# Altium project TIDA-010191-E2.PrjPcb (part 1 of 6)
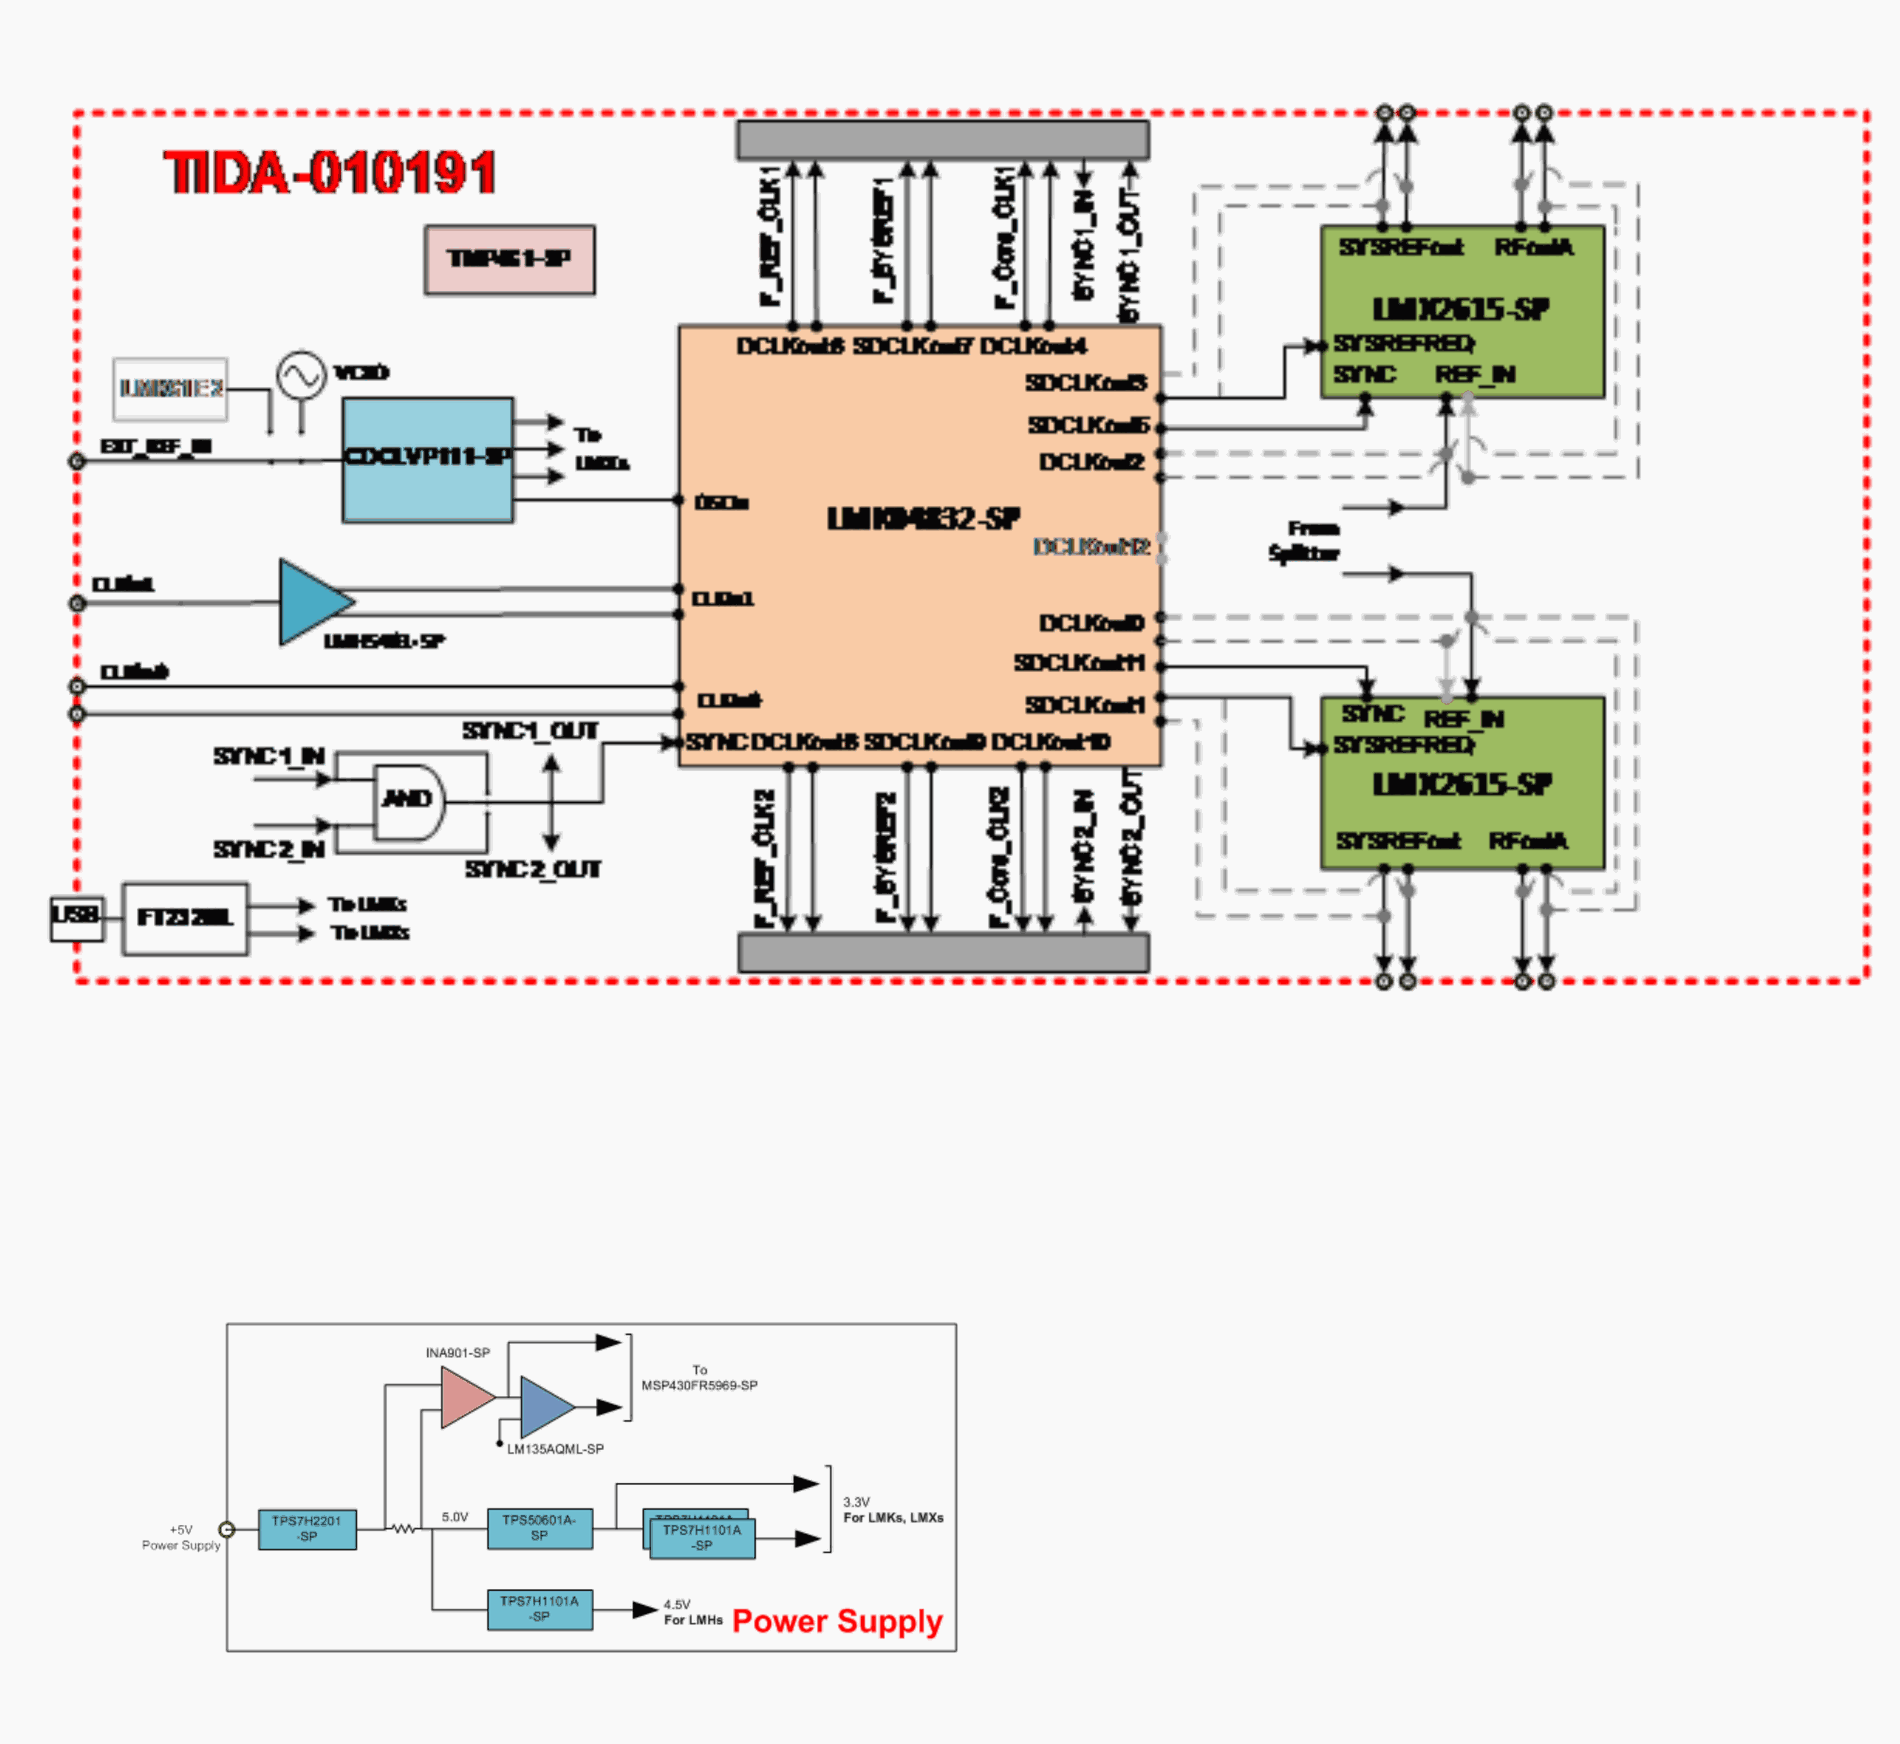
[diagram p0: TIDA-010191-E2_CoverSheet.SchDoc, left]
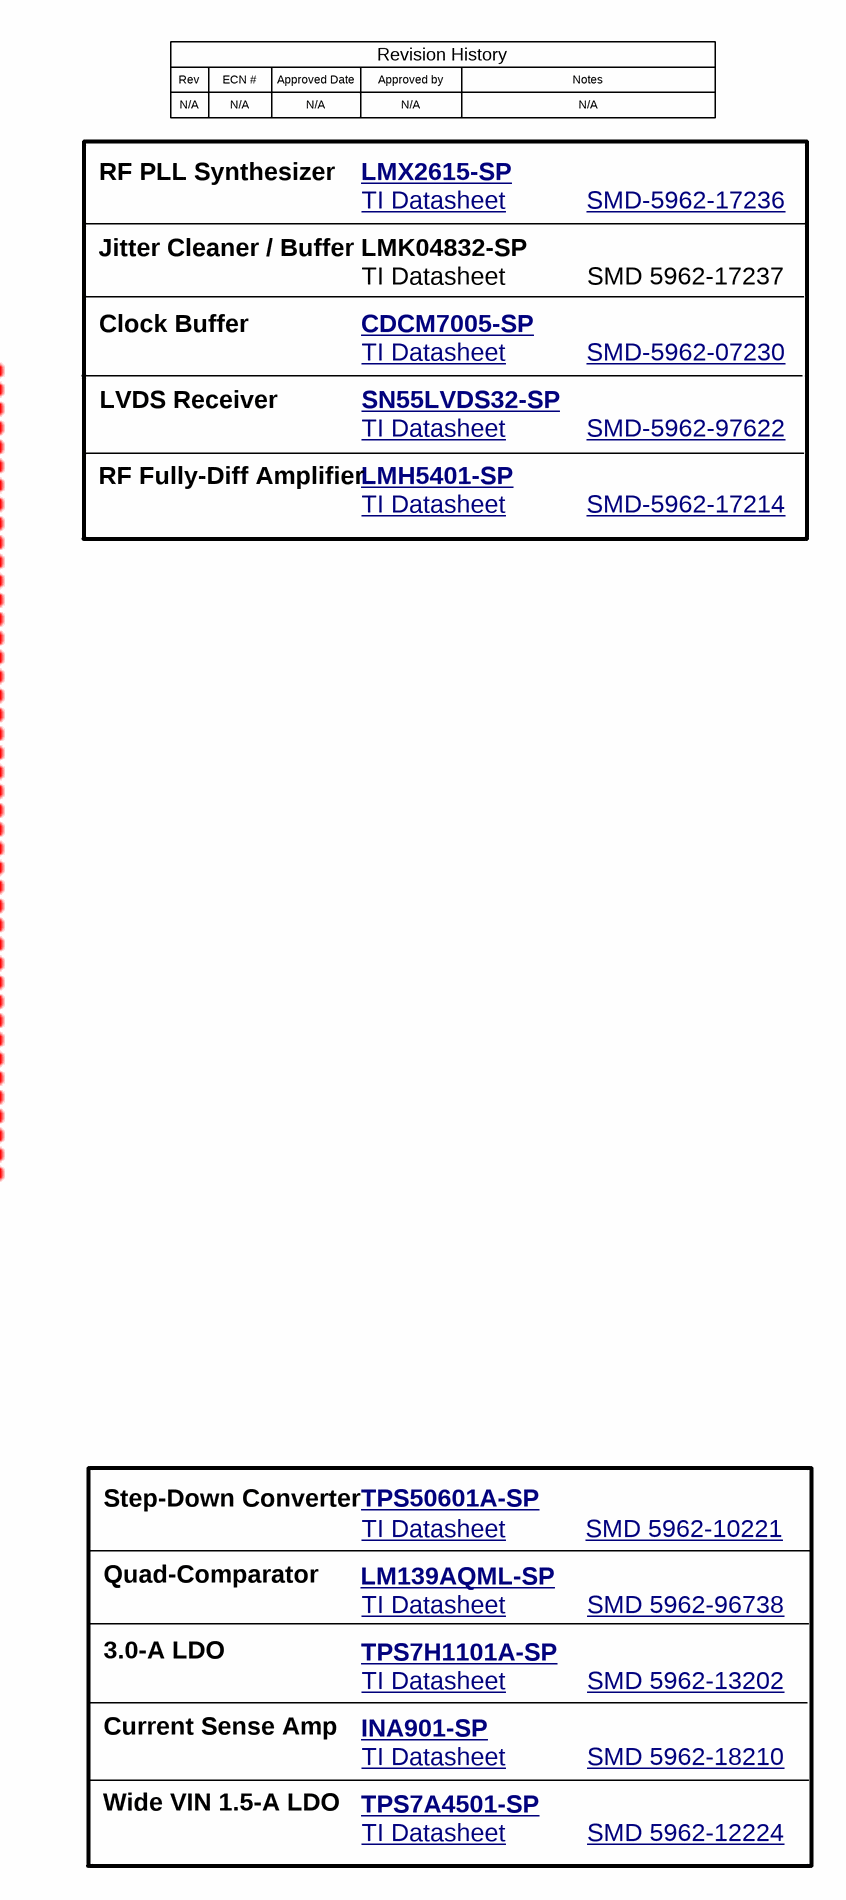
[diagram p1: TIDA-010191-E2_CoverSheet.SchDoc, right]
CopyrightYear: 2019; EVM_orderable: NA; PCB_Layout: TBD; PCB_Rev: E2; PRJ_Customer: Public Release; PRJ_Engineer: Victor Salomon; PRJ_Number: TIDA-010191; PRJ_Title: TIDA-010191; SCH_Rev: E2; TechSupport: http://e2e.ti.com/; TID: 010191
9 sheets, 1179 parts. Net scope: flat (ports and power ports of the same name join across sheets).
Board file: TIDA-010191-E2b3.PcbDoc
Sheets:
  TIDA-010191-E2_CoverSheet.SchDoc
  TIDA-010191-E2_LMK04832.SchDoc
  TIDA-010191-E2_CDCLVP111.SchDoc
  TIDA-010191-E2_LMX2615.SchDoc
  TIDA-010191-E2_LMX2615_LO.SchDoc
  TIDA-010191-E2_Power-Supply_1.SchDoc
  TIDA-010191-E2_Power-Supply_2.SchDoc
  TIDA-010191-E2_USB.SchDoc
  TIDA-010191-E2_Hardware.SchDoc

## Sheet TIDA-010191-E2_CoverSheet.SchDoc
size 558 x 431 mm; Date: Not shown in title block; ApprovedBy: Not shown in title block; CheckedBy: Not shown in title block; Author: Not shown in title block; CompanyName: Not shown in title block; DrawnBy: Avinash N; Engineer: Not shown in title block; Organization: Not shown in title block; Address1: Not shown in title block; Address2: Not shown in title block; Address3: Not shown in title block; Address4: Not shown in title block; DocumentNumber: 1; Revision: Use project parameter SCH_Rev; SheetNumber: 1; SheetTotal: 9; PageSetup: Record=PageOptions¦CenterHorizontal=True¦CenterVertical=True¦PrintScale=1.00¦XCorrection=1.00¦YCorrection=1.00¦PrintKind=0¦BorderSize=5000000¦LeftOffset=0¦BottomOffset=0¦Orientation=2¦PaperLength=1000¦PaperWidth=1000¦Scale=100¦PaperSource=15¦PrintQuality=600¦MediaType=1¦DitherType=10¦PaperKind=Letter¦PrintScaleMode=1

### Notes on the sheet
- Revision History
- Rev
- N/A
- ECN #
- Approved Date
- Approved by
- Notes
- RF PLL Synthesizer
- LMX2615-SP <http://www.ti.com/product/LMX2615-SP>
- Jitter Cleaner / Buffer
- TI Datasheet <http://www.ti.com/lit/gpn/lmx2615-sp>
- LMK04832-SP
- SMD-5962-17236 <https://landandmaritimeapps.dla.mil/Downloads/MilSpec/Smd/17236.pdf>
- TI Datasheet
- SMD 5962-17237
- Clock Buffer
- TI Datasheet <http://www.ti.com/lit/gpn/cdcm7005-sp>
- CDCM7005-SP <http://www.ti.com/product/CDCM7005-SP>
- SMD-5962-07230 <https://landandmaritimeapps.dla.mil/Downloads/MilSpec/Smd/07230.pdf>
- LVDS Receiver
- TI Datasheet <http://www.ti.com/lit/gpn/sn55lvds32-sp>
- SN55LVDS32-SP <http://www.ti.com/product/SN55LVDS32-SP>
- SMD-5962-97622 <https://landandmaritimeapps.dla.mil/Downloads/MilSpec/Smd/97622.pdf>
- RF Fully-Diff Amplifier
- TI Datasheet <http://www.ti.com/lit/gpn/lmh5401-sp>
- LMH5401-SP <http://www.ti.com/product/LMH5401-SP>
- SMD-5962-17214 <https://landandmaritimeapps.dla.mil/Downloads/MilSpec/Smd/17214.pdf>
- Step-Down Converter
- TPS50601A-SP <http://www.ti.com/product/TPS50601A-SP>
- Quad-Comparator
- TI Datasheet <http://www.ti.com/lit/gpn/tps50601a-sp>
- LM139AQML-SP <http://www.ti.com/product/LM139AQML-SP>
- SMD 5962-10221 <https://landandmaritimeapps.dla.mil/Downloads/MilSpec/Smd/10221.pdf>
- TI Datasheet <http://www.ti.com/lit/gpn/lm139aqml-sp>
- SMD 5962-96738 <https://landandmaritimeapps.dla.mil/Downloads/MilSpec/Smd/96738.pdf>
- 3.0-A LDO
- TI Datasheet <http://www.ti.com/lit/gpn/TPS7H1101A-SP>
- TPS7H1101A-SP <http://www.ti.com/product/TPS7H1101A-SP>
- SMD 5962-13202 <https://landandmaritimeapps.dla.mil/Downloads/MilSpec/Smd/13202.pdf>
- Current Sense Amp
- INA901-SP <http://www.ti.com/product/INA901-SP>
- TI Datasheet <http://www.ti.com/lit/gpn/INA901-SP>
- SMD 5962-18210 <https://landandmaritimeapps.dla.mil/Downloads/MilSpec/Smd/18210.pdf>
- Wide VIN 1.5-A LDO
- TI Datasheet <http://www.ti.com/lit/gpn/TPS7A4501-SP>
- TPS7A4501-SP <http://www.ti.com/product/TPS7A4501-SP>
- SMD 5962-12224 <https://landandmaritimeapps.dla.mil/Downloads/MilSpec/Smd/12224.pdf>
